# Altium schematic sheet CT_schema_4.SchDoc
size 293 x 258 mm
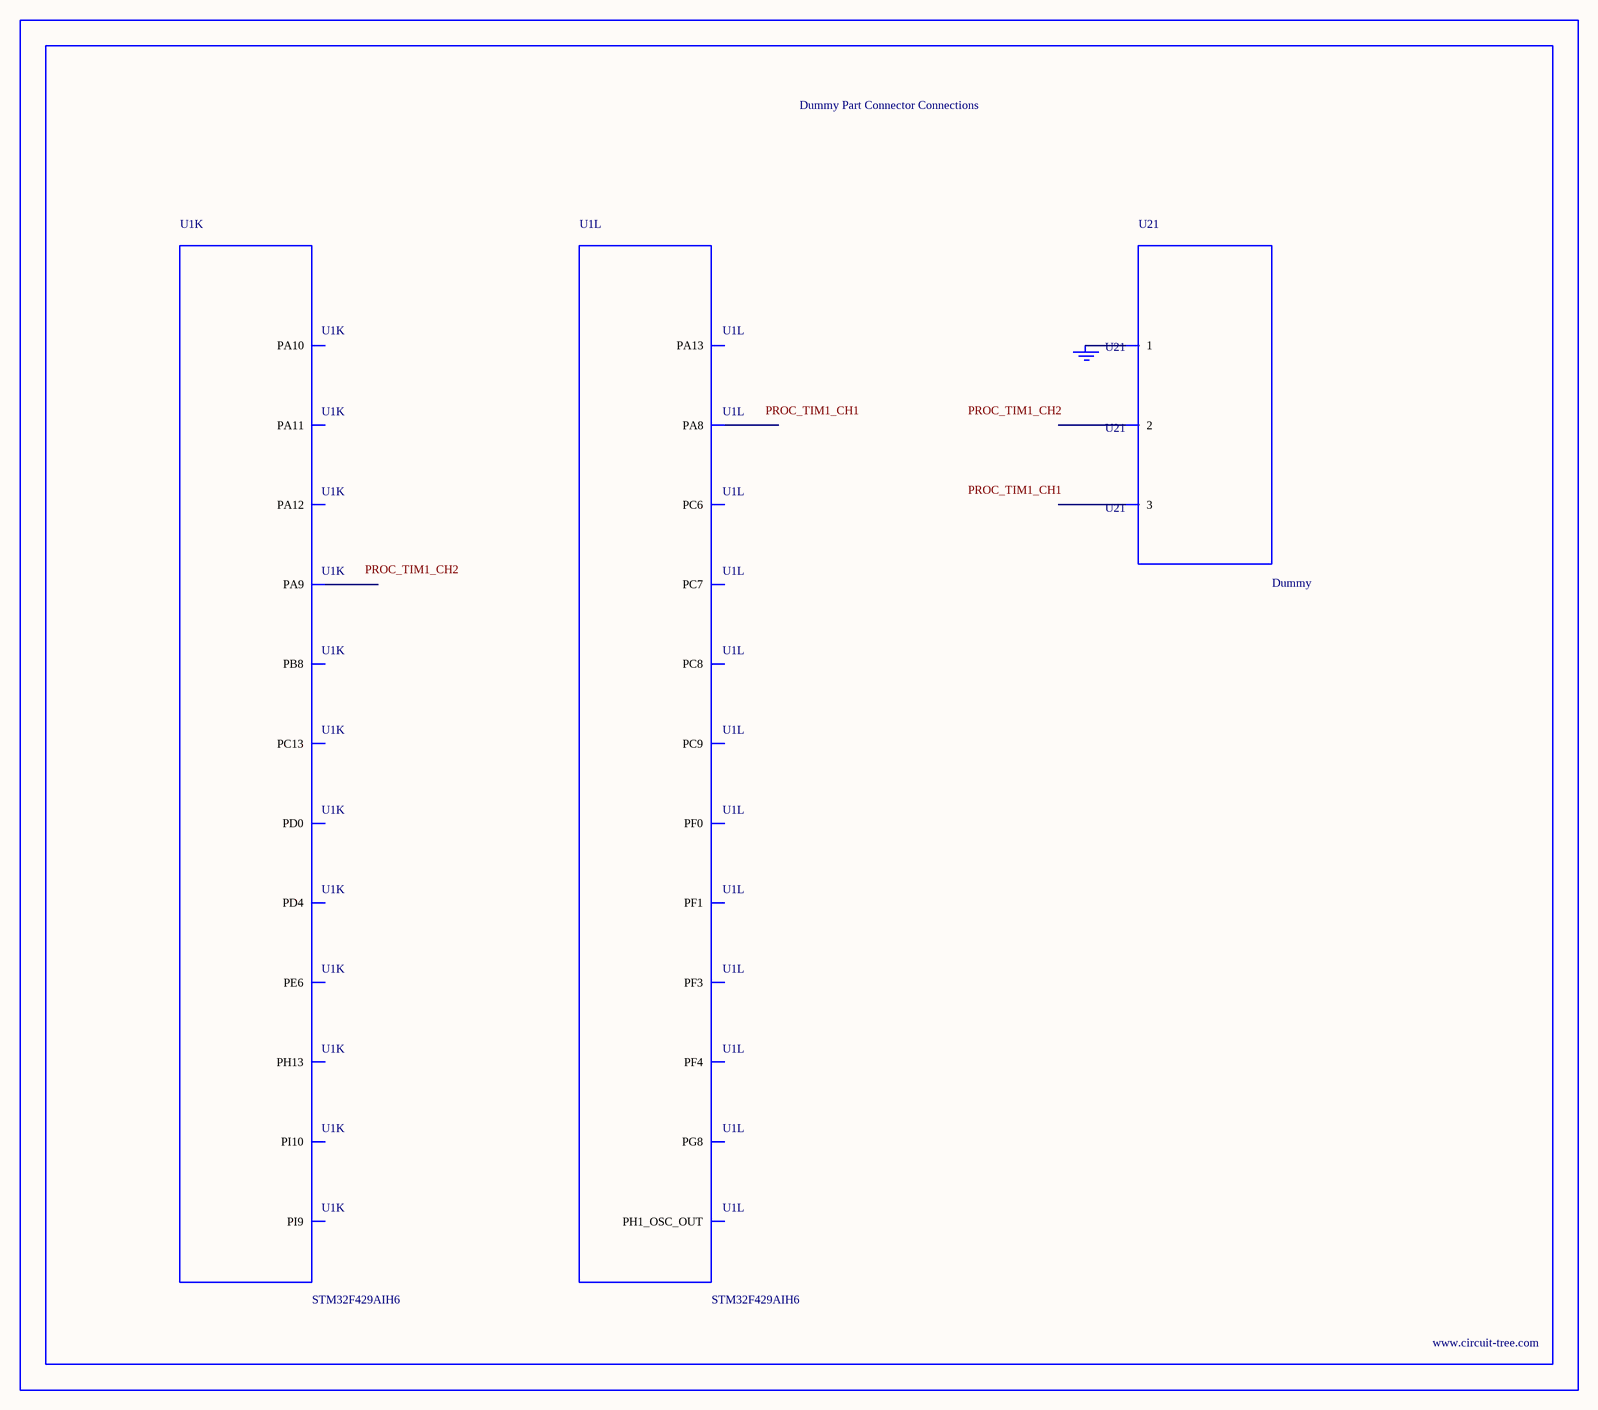
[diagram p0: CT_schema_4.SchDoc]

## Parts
BORDER3  (no value)
GND_INSTANCE_3_0  (no value)
U1  STM32F429AIH6  [UFBGA169]  (parts K,L of 12)
U21  Dummy  [DUMMY_PACKAGE_236]

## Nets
NetGND_INSTANCE_3_0_0: GND_INSTANCE_3_0.0(GND) U21.1

Not connected (* = marked no-connect by the designer): U1 D2(PE6) D4(PB8) D8(PD4) D9(PD0) D13(PH13) E2(PI9) E3(PI10) E4(PC13) E8(PA9) E9(PA10) E10(PA11) E11(PA12) E12(PA13) E13(PA8) F2(PF0) F3(PF1) F9(PC6) F10(PC7) F11(PC8) F12(PC9) F13(PG8) G1(PH1_OSC_OUT) G3(PF4) G4(PF3); U21 2 3

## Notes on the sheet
- Labels drawn without touching a wire or pin: PROC_TIM1_CH1, PROC_TIM1_CH2

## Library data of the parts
BORDER3 = BORDER_PAGE3
GND_INSTANCE_3_0 = GND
